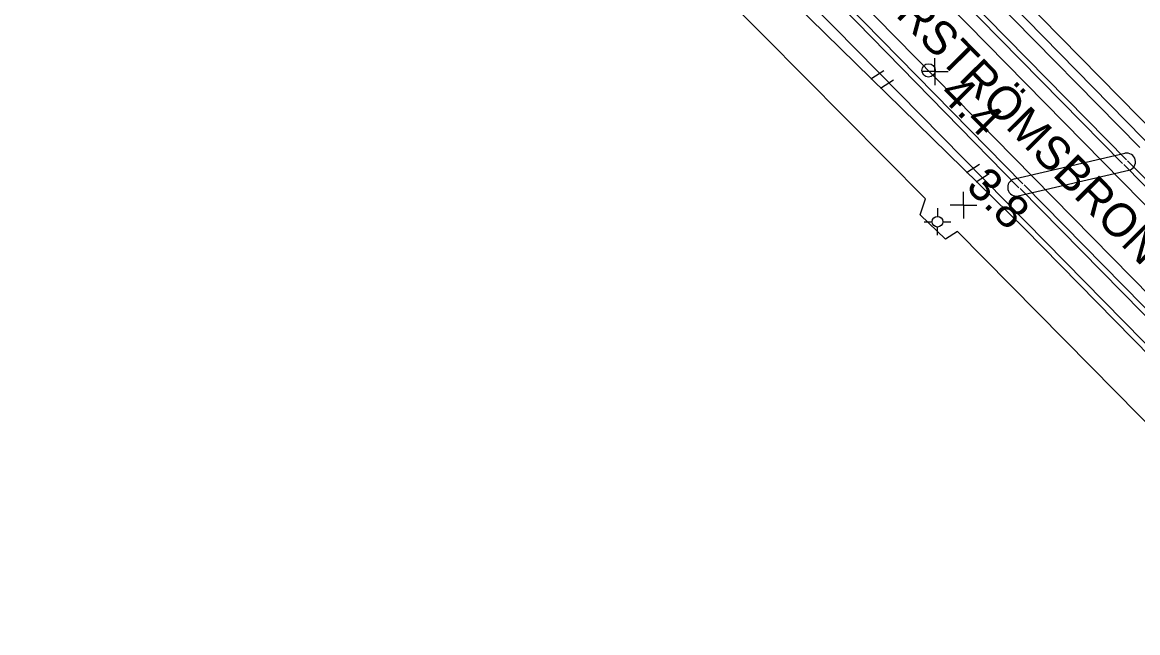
# Model space of a CAD drawing. Extents: x 1596643 to 1597288, y 13057194 to 13057957.
# Drawn here: x 1596964.2 to 1597047.6, y 13057293 to 13057338.6 of the extents above; entities that cross this region are included whole.
import ezdxf

# ---------------------------------------------------------------- set-up
doc = ezdxf.new("R2010")
doc.units = 0
for name, color, linetype in [('A spårmitt L', 7, 'Continuous'), ('BAS belysningsstolpe P', 7, 'Continuous'), ('BAS bro kantbalk ej def L', 7, 'Continuous'), ('BAS bropelare stöd ej def L', 7, 'Continuous'), ('BAS jvg-bro kantbalk L', 7, 'Continuous'), ('BAS Level 15', 7, 'Continuous'), ('BAS Level 16', 7, 'Continuous'), ('BAS Level 19', 7, 'Continuous'), ('BAS markytetext T', 7, 'Continuous'), ('BAS staket plank lågt L', 7, 'Continuous'), ('BAS väg T', 7, 'Continuous'), ('BAS vägbanekant L', 7, 'Continuous')]:
    doc.layers.add(name, color=color, linetype=linetype)

msp = doc.modelspace()

# ---------------------------------------------------------------- linework, layer by layer
at = {"layer": 'A spårmitt L'}
for points in [[(1596887.988, 13057492.75), (1596889.66, 13057490.516), (1596900.094, 13057476.776), (1596906.53, 13057469.464), (1596928.328, 13057446.663), (1596936.899, 13057437.942), (1596957.336, 13057417.351), (1597001.928, 13057371.989), (1597034.879, 13057338.506), (1597063.764, 13057309.15)], [(1596933.802, 13057434.837), (1596974.458, 13057393.515), (1596978.362, 13057389.553), (1596998.703, 13057368.849), (1597057.437, 13057309.15)]]:
    msp.add_lwpolyline(points, dxfattribs=at)
at = {"layer": 'BAS belysningsstolpe P'}
for p, q in [((1597032.638, 13057324.742), (1597032.638, 13057324.142)), ((1597032.638, 13057324.742), (1597032.638, 13057324.142)), ((1597031.638, 13057323.742), (1597032.238, 13057323.742)), ((1597031.638, 13057323.742), (1597032.238, 13057323.742)), ((1597033.037, 13057323.742), (1597033.638, 13057323.742)), ((1597033.037, 13057323.742), (1597033.638, 13057323.742)), ((1597032.638, 13057322.742), (1597032.638, 13057323.344)), ((1597032.638, 13057322.742), (1597032.638, 13057323.344))]:
    msp.add_line(p, q, dxfattribs=at)
msp.add_circle((1597032.638, 13057323.742), 0.4, dxfattribs=at)
msp.add_circle((1597032.638, 13057323.742), 0.4, dxfattribs=at)
at = {"layer": 'BAS bro kantbalk ej def L'}
for p, q in [((1597024.97, 13057338.226), (1596997.782, 13057365.837)), ((1597034.414, 13057342.845), (1597047.766, 13057329.296)), ((1597046.472, 13057328.087), (1597033.221, 13057341.565)), ((1597033.505, 13057341.845), (1597046.756, 13057328.367)), ((1597038.729, 13057326.285), (1597025.511, 13057339.762)), ((1597039.015, 13057326.566), (1597025.797, 13057340.042)), ((1597037.776, 13057325.218), (1597024.97, 13057338.226)), ((1597059.818, 13057314.533), (1597046.559, 13057328.011)), ((1597046.844, 13057328.291), (1597060.103, 13057314.813)), ((1597052.367, 13057313.027), (1597039.106, 13057326.499)), ((1597065.419, 13057299.188), (1597038.821, 13057326.218)), ((1597051.108, 13057311.666), (1597037.776, 13057325.218))]:
    msp.add_line(p, q, dxfattribs=at)
for points in [[(1597031.744, 13057325.449), (1597019.684, 13057337.598), (1597007.4, 13057349.92), (1597006.374, 13057349.4), (1597004.663, 13057351.16), (1597005.204, 13057352.357), (1596994.028, 13057363.747)], [(1597125.051, 13057230.538), (1597087.533, 13057268.722), (1597086.313, 13057268.276), (1597084.579, 13057270.108), (1597085.087, 13057271.349), (1597067.863, 13057288.791), (1597060.82, 13057295.894), (1597059.791, 13057295.319), (1597057.864, 13057297.218), (1597058.481, 13057298.366), (1597044.109, 13057312.935), (1597034.132, 13057323.01), (1597033.23, 13057322.446), (1597031.336, 13057324.261), (1597031.744, 13057325.449)]]:
    msp.add_lwpolyline(points, dxfattribs=at)
at = {"layer": 'BAS bropelare stöd ej def L'}
for p, q in [((1597038.387, 13057326.941), (1597046.646, 13057328.851)), ((1597038.676, 13057325.673), (1597046.937, 13057327.584))]:
    msp.add_line(p, q, dxfattribs=at)
for centre, start, end in [((1597046.79, 13057328.218), 283.02596, 103.02572), ((1597038.534, 13057326.307), 103.02596, 283.02572)]:
    msp.add_arc(centre, 0.65, start, end, dxfattribs=at)
at = {"layer": 'BAS jvg-bro kantbalk L'}
msp.add_line((1597038.048, 13057340.116), (1597049.265, 13057328.698), dxfattribs=at)
at = {"layer": 'BAS Level 15'}
msp.add_circle((1597031.973, 13057335.049), 0.5, dxfattribs=at)
msp.add_circle((1597031.973, 13057335.049), 0.5, dxfattribs=at)
at = {"layer": 'BAS Level 16'}
for p, q in [((1597032.437, 13057334.955), (1597032.437, 13057335.955)), ((1597032.437, 13057334.955), (1597032.437, 13057335.955)), ((1597032.437, 13057334.955), (1597031.437, 13057334.955)), ((1597032.437, 13057334.955), (1597031.437, 13057334.955)), ((1597032.437, 13057334.955), (1597033.437, 13057334.955)), ((1597032.437, 13057334.955), (1597032.437, 13057333.955)), ((1597032.437, 13057334.955), (1597033.437, 13057334.955)), ((1597032.437, 13057334.955), (1597032.437, 13057333.955)), ((1597034.584, 13057324.974), (1597034.584, 13057325.974)), ((1597034.584, 13057324.974), (1597034.584, 13057325.974)), ((1597034.584, 13057324.974), (1597033.584, 13057324.974)), ((1597034.584, 13057324.974), (1597033.584, 13057324.974)), ((1597034.584, 13057324.974), (1597035.584, 13057324.974)), ((1597034.584, 13057324.974), (1597034.584, 13057323.974)), ((1597034.584, 13057324.974), (1597035.584, 13057324.974)), ((1597034.584, 13057324.974), (1597034.584, 13057323.974))]:
    msp.add_line(p, q, dxfattribs=at)
at = {"layer": 'BAS Level 19'}
for p, q in [((1597027.662, 13057334.412), (1597028.637, 13057335.044)), ((1597027.662, 13057334.412), (1597028.637, 13057335.044)), ((1597028.376, 13057333.713), (1597029.351, 13057334.345)), ((1597028.376, 13057333.713), (1597029.351, 13057334.345)), ((1597034.809, 13057327.418), (1597035.784, 13057328.05)), ((1597034.809, 13057327.418), (1597035.784, 13057328.05)), ((1597035.523, 13057326.719), (1597036.498, 13057327.351)), ((1597035.523, 13057326.719), (1597036.498, 13057327.351))]:
    msp.add_line(p, q, dxfattribs=at)
at = {"layer": 'BAS staket plank lågt L'}
for points in [[(1597039.139, 13057323.227), (1597023.086, 13057338.935), (1597002.12, 13057360.315), (1596996.958, 13057365.38)], [(1597039.139, 13057323.227), (1597066.172, 13057295.728)], [(1597129.454, 13057231.151), (1597099.093, 13057262.326), (1597066.172, 13057295.728), (1597039.139, 13057323.227)]]:
    msp.add_lwpolyline(points, dxfattribs=at)
at = {"layer": 'BAS vägbanekant L'}
msp.add_line((1597049.171, 13057330.064), (1597037.913, 13057341.517), dxfattribs=at)

# ---------------------------------------------------------------- texts
at = {"layer": 'BAS markytetext T'}
for s, p in [('4.4', (1597032.68, 13057333.2)), ('3.8', (1597034.68, 13057326.277))]:
    msp.add_text(s, height=2.5, rotation=315, dxfattribs=at).set_placement(p)
at = {"layer": 'BAS väg T'}
msp.add_text('NORRSTRÖMSBRON', height=2.5, rotation=314.541, dxfattribs=at).set_placement((1597024.235, 13057344.435))

doc.saveas('drawing.dxf')
